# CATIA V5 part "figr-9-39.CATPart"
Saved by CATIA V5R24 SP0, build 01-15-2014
Part number: Part1
Bounding box of the stored display mesh (mm): x -40 to 40, y -20 to 191.034, z 0 to 131.022
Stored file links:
  D:\KAVITA\CATIA V5-6R2014 Project_ Kavita\CATIA V5-6R2014_partfiles\Partfiles\c09_catia_v5-6r2014_prt\figr-9-39.CATPart
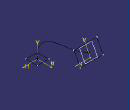
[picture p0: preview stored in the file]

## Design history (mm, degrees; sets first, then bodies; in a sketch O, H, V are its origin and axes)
Set1
  Plane1: type Normal, Curve Sketch2, RefPoint vertex of Sketch2
Body1 (main body)
  Sketch1 on xy-plane, origin (0, 0, 0), H (1, 0, 0), V (0, 1, 0)
    line L1 (20, 20) -> (20, -20)
    line L2 (20, -20) -> (-20, -20)
    line L3 (-20, -20) -> (-20, 20)
    line L4 (-20, 20) -> (20, 20)
    vertical: L1 V, L3 V
    horizontal: L2 H, L4 H
    equidistance: L1 L3 O, L2 L4 O
  Sketch2 on yz-plane, origin (0, 0, 0), H (0, 1, 0), V (0, 0, 1)
    spline S1 through (0, 0) (20, 60) (60, 80) (120, 90) (180, 110)
    point P1 (0, 0)
    coincidence: P1 O
  Sketch3 on Plane1, origin (0, 186.3865, 97.8327), H (1, 0, 0), V (0, -0.4648, 0.8854)
    point P1 (0, 13.7415)
    line L1 (40, 37.4831) -> (40, -10)
    line L2 (40, -10) -> (-40, -10)
    line L3 (-40, -10) -> (-40, 37.4831)
    line L4 (-40, 37.4831) -> (40, 37.4831)
    reference projected point E1 (0, 13.7415) from vertex of Sketch2
    coincidence: P1 V, P1 E1
    vertical: L1 V, L3 V
    horizontal: L2 H, L4 H
    equidistance: L1 L3 P1, L2 L4 P1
